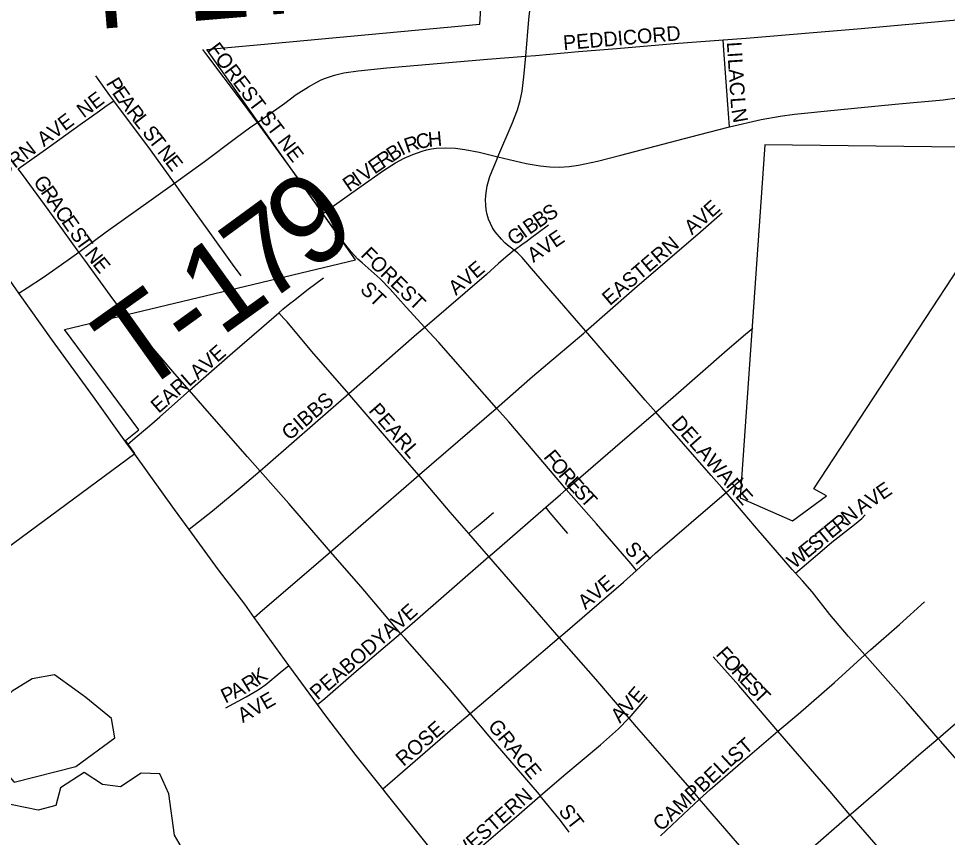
# Model space of a CAD drawing. Extents: x -51392 to 1635000, y 156707 to 696232.
# Drawn here: x 135989 to 139153, y 489385 to 492173 of the extents above; entities that cross this region are included whole.
import ezdxf

# ---------------------------------------------------------------- set-up
doc = ezdxf.new("R2010")
doc.units = 0
for name, color, linetype in [('GM_X_City_Street', 7, 'Continuous'), ('GM_X_City_Street_Text', 7, 'Continuous'), ('GM_X_Corporation', 7, 'Continuous'), ('GM_X_Major_River', 7, 'Continuous'), ('GM_X_Minor_Lake', 7, 'Continuous'), ('GM_X_State_Route', 7, 'Continuous'), ('GM_X_Township_Road', 7, 'Continuous'), ('GM_X_Township_Road_Text', 7, 'Continuous'), ('GM_X_Township_Subdivision', 7, 'Continuous'), ('GM_X_Township_Subdivision_Text', 7, 'Continuous')]:
    doc.layers.add(name, color=color, linetype=linetype)

msp = doc.modelspace()

# ---------------------------------------------------------------- linework, layer by layer
at = {"layer": 'GM_X_City_Street'}
for points in [[(137716.9, 492044.3), (137727.4, 492169.8), (137741.8, 492300), (137744, 492323.6)], [(138389, 492100.2), (138467.7, 492106.2), (138696, 492125.6), (138859.1, 492139.3), (139185.2, 492168.5), (139217.9, 492169.8), (139234.3, 492169.4), (139250.6, 492167.7), (139266.6, 492164.7), (139282.3, 492160), (139297.3, 492153.7), (139311.8, 492146), (139338.8, 492127.6), (139365.5, 492108.6), (139403.9, 492081.4)], [(137716.9, 492044.3), (137749.9, 492046.9), (137896.6, 492060.1), (138027.2, 492070.8), (138222.9, 492087.5), (138389, 492100.2)], [(138411.3, 491804.6), (138407.9, 491849.3), (138391.7, 492065), (138389, 492100.2)], [(138411.3, 491804.6), (138518.5, 491829.1), (138583.2, 491840.3), (138632, 491846.8), (138779.1, 491861.4), (138975.1, 491880.8), (139138.6, 491896.4), (139187.5, 491902.4), (139219.7, 491908.9), (139251.1, 491918.4), (139266.2, 491924.9), (139280.5, 491932.9), (139294, 491942.2), (139306.6, 491952.8), (139318.2, 491964.4), (139339.1, 491989.7), (139403.9, 492081.4)], [(136803.3, 491818.9), (136896.5, 491884.1), (136935.5, 491913.9), (136976.6, 491940.7), (137005.2, 491956.7), (137019.8, 491964), (137034.9, 491970.3), (137066.1, 491980.3), (137097.9, 491987.6), (137146.6, 491994.3), (137244.2, 492004.7), (137586.7, 492034.2), (137716.9, 492044.3)], [(137622.4, 491702.2), (137671, 491815.9), (137688.5, 491861.8), (137697.6, 491893.2), (137704.4, 491925.2), (137710.9, 491973.9), (137716.9, 492044.3)], [(137622.4, 491702.2), (137718.1, 491679.6), (137766.6, 491670.9), (137799.2, 491667.5), (137832, 491666.6), (137864.8, 491668.8), (137897.2, 491674), (137961.3, 491687.3), (138040.9, 491708.2), (138279.3, 491770.4), (138406.5, 491803.5), (138411.3, 491804.6)], [(137025.8, 491508.9), (137058, 491531.8), (137151.9, 491598.2), (137232, 491655.4), (137273.8, 491681.5), (137302.7, 491697.1), (137332.7, 491710.4), (137363.7, 491721.4), (137379.5, 491725.9), (137395.5, 491729.3), (137411.8, 491731.4), (137444.6, 491732.8), (137477.4, 491731.4), (137510, 491727.3), (137558.2, 491717.3), (137622.4, 491702.2)], [(137677.7, 491384), (137655.1, 491400.7), (137645.3, 491409.5), (137634, 491421.4), (137613.2, 491446.7), (137604.1, 491460.3), (137596.4, 491474.8), (137590.2, 491489.9), (137585.4, 491505.6), (137582.4, 491521.7), (137580.8, 491538), (137580.4, 491554.3), (137581, 491570.7), (137583, 491587), (137586, 491603.1), (137595.2, 491634.5), (137619.5, 491695.4), (137622.4, 491702.2)], [(137921.9, 491108.3), (138088, 491253.6), (138312.1, 491446.3), (138386.3, 491511)], [(137677.7, 491384), (137708.3, 491406.8), (137716.8, 491412.9), (137737.6, 491428.8), (137754.7, 491441.5), (137794, 491470.6)], [(137677.7, 491384), (137641.4, 491354), (137624.7, 491339), (137583.2, 491301.6), (137373.1, 491120.9)], [(137921.9, 491108.3), (137898.2, 491135.8), (137736.7, 491322.3), (137705.1, 491359.3), (137689.7, 491373.6), (137677.7, 491384)], [(137373.1, 491120.9), (137309.7, 491190.1), (137281.2, 491222), (137255.1, 491251.1), (137220.9, 491286.4), (137160.3, 491341.4), (137145.5, 491353.8)], [(136875.9, 491171.2), (136889.7, 491183.4), (136913.9, 491202.5), (136925.9, 491212.2), (136975.5, 491251.9), (137028.5, 491290.4)], [(136571.5, 490906.6), (136521.2, 490963.7), (136415.4, 491088.3), (136320.6, 491205)], [(136571.5, 490906.6), (136619.3, 490948.8), (136718.2, 491034.4), (136817.4, 491119.6), (136875.9, 491171.2)], [(137114.4, 490895.7), (136988.5, 491039.4), (136903.9, 491139.8), (136893, 491152), (136875.9, 491171.2)], [(137373.1, 491120.9), (137346.3, 491097.9), (137114.4, 490895.7)], [(137617.7, 490846.5), (137420.4, 491069.6), (137373.1, 491120.9)], [(138159.6, 490832.4), (138219.1, 490883.7), (138403.1, 491045.4), (138465.3, 491097.9), (138490.6, 491118.3)], [(137617.7, 490846.5), (137739.6, 490953.7), (137915, 491102.2), (137921.9, 491108.3)], [(138159.6, 490832.4), (138123.6, 490873.6), (137921.9, 491108.3)], [(136443.1, 490792.5), (136470.6, 490816.9), (136571.5, 490906.6)], [(136811.9, 490631.7), (136768.7, 490680.6), (136640.1, 490828.7), (136571.5, 490906.6)], [(137114.4, 490895.7), (136999.3, 490795.4), (136838.7, 490654.5), (136811.9, 490631.7)], [(137352.5, 490617.9), (137300, 490679.7), (137118.1, 490891.1), (137114.4, 490895.7)], [(137352.5, 490617.9), (137355.2, 490620), (137616.3, 490845.2), (137617.7, 490846.5)], [(137855.1, 490569.8), (137839.4, 490587.9), (137659.2, 490799.9), (137617.7, 490846.5)], [(137855.1, 490569.8), (138021.2, 490713.1), (138159.6, 490832.4)], [(138399.6, 490559.2), (138384.4, 490576.5), (138348.8, 490616.9), (138159.6, 490832.4)], [(136811.9, 490631.7), (136750.9, 490580), (136649.6, 490495.8), (136570.4, 490433.8)], [(137051.7, 490357.7), (137038.2, 490373.4), (136909.5, 490521.4), (136811.9, 490631.7)], [(137051.7, 490357.7), (137352.5, 490617.9)], [(137523.1, 490419.7), (137459.5, 490492.2), (137352.5, 490617.9)], [(138399.6, 490559.2), (138457.2, 490608.8)], [(139121.4, 489722.3), (139180.9, 489772.6), (139364.6, 489936), (139488.8, 490043), (139760.9, 490279.3), (139896.1, 490398.7), (140115.2, 490590.7)], [(137785, 490509.1), (137835.7, 490553), (137855.1, 490569.8)], [(138094.8, 490294.2), (138075.7, 490316.1), (137957.7, 490452.1), (137855.1, 490569.8)], [(138094.8, 490294.2), (138159.2, 490352.2), (138345.5, 490512.4), (138399.6, 490559.2)], [(138515.6, 490423.4), (138399.6, 490559.2)], [(137523.1, 490419.7), (137543, 490436.4), (137568.8, 490458), (137607.4, 490490.8)], [(137591.6, 490341.4), (137601.2, 490349.8), (137785, 490509.1)], [(137860, 490419.6), (137800.5, 490490.6), (137785, 490509.1)], [(138636.1, 490284.5), (138710.3, 490347.9), (138760.1, 490389.8), (138837.1, 490449.9), (138861.5, 490471.3), (138873.3, 490482.7)], [(137591.6, 490341.4), (137567.8, 490368.9), (137523.1, 490419.7)], [(138636.1, 490284.5), (138624.9, 490297.3), (138518.1, 490420.5), (138515.6, 490423.4)], [(136792, 490134.1), (136820.6, 490158.8), (136970.1, 490287.2), (137051.7, 490357.7)], [(137290.9, 490079.8), (137230.5, 490150.6), (137156.8, 490238.1), (137051.7, 490357.7)], [(137290.9, 490079.8), (137330.6, 490113.4), (137591.6, 490341.4)], [(137831.3, 490066.1), (137718.4, 490195.4), (137591.6, 490341.4)], [(137831.3, 490066.1), (137850.8, 490082.7), (138049.6, 490253.6), (138094.8, 490294.2)], [(138872.3, 490006.5), (138816.9, 490068.7), (138753.3, 490144.1), (138692.4, 490221.3), (138660, 490258), (138636.1, 490284.5)], [(138872.3, 490006.5), (138891, 490023.1), (138990.2, 490109.6), (139075.3, 490187.1)], [(137008.2, 489837), (137032.8, 489858.5), (137131, 489944.7), (137230.9, 490029), (137290.9, 490079.8)], [(137527.6, 489806.8), (137456, 489891.9), (137304.8, 490063.6), (137290.9, 490079.8)], [(137527.6, 489806.8), (137589.4, 489859), (137713.8, 489965.6), (137831.3, 490066.1)], [(138068.8, 489791.3), (137955.9, 489923.5), (137831.3, 490066.1)], [(138575.9, 489746.7), (138644.5, 489805.2), (138768.9, 489912.8), (138872.3, 490006.5)], [(139121.4, 489722.3), (139013.3, 489848.2), (138872.3, 490006.5)], [(138575.9, 489746.7), (138549.7, 489777.3), (138443, 489902.1), (138355.4, 490000.1)], [(136695.5, 489825.8), (136765.1, 489863.3), (136805.7, 489887.8), (136831.5, 489906.1), (136880.4, 489946.3), (136909.7, 489970.4)], [(138068.8, 489791.3), (138110.6, 489838.3), (138131.7, 489863.3)], [(137229.9, 489550.4), (137253.8, 489570.9), (137340.7, 489645.7), (137476.8, 489763.9), (137527.6, 489806.8)], [(137766.6, 489526.9), (137763.4, 489530.9), (137592.8, 489729.3), (137527.6, 489806.8)], [(137766.6, 489526.9), (137846.2, 489595.3), (137971.9, 489699.9), (138032.5, 489754.8), (138067.1, 489789.5), (138068.8, 489791.3)], [(138309.2, 489515), (138299.4, 489526.4), (138213.1, 489625.3), (138094.5, 489761.3), (138068.8, 489791.3)], [(138309.2, 489515), (138345.1, 489547.8), (138456.7, 489645.1), (138575.9, 489746.7)], [(138821.3, 489462.1), (138753.8, 489541.1), (138575.9, 489746.7)], [(138821.3, 489462.1), (138833.8, 489472.5), (138969.8, 489590.7), (139055.8, 489666.7), (139121.4, 489722.3)], [(139390.1, 489412.2), (139271.3, 489550.7), (139130.7, 489711.2), (139121.4, 489722.3)], [(137460.9, 489264.5), (137486.4, 489286.4), (137685, 489456.7), (137766.6, 489526.9)], [(137864.8, 489402.8), (137835.8, 489442.4), (137766.6, 489526.9)], [(138176.6, 489390.7), (138272.5, 489480.9), (138309.2, 489515)], [(138554.9, 489230.4), (138546, 489240.6), (138309.2, 489515)], [(138554.9, 489230.4), (138722, 489376.2), (138821.3, 489462.1)], [(139091.4, 489153.1), (138947.1, 489317.6), (138828.4, 489453.7), (138821.3, 489462.1)]]:
    msp.add_lwpolyline(points, dxfattribs=at)
at = {"layer": 'GM_X_Corporation'}
for points in [[(135520.3, 492188.3), (135566.7, 491914.9), (135580.3, 491867.6), (135603.4, 491805.1), (133833.5, 492028.3), (133821, 491861.8), (133926.1, 490810), (134830.5, 491047.4), (135185.7, 490756.7), (134987.1, 490585.9), (135134.2, 490381.2), (135761.9, 490232.9), (136385.4, 490691.9), (136353.3, 490736), (136399.6, 490772.9), (136145.5, 491114.3), (137137, 491351.3), (136630.3, 492067), (136652.2, 492069.4), (136801.6, 492083.2), (137560.3, 492153.6), (137599.5, 492759.5)], [(139780.3, 492322.4), (139382.9, 491732.9), (138531.2, 491743.3), (138447.1, 490541.3), (138625.9, 490463), (138741, 490547.5), (138698.5, 490572.2), (139573.9, 491906.7), (139880, 491837.7), (139911.2, 491565.8), (140072.1, 491715), (140073.3, 491866.9), (140221.8, 491863.1), (140226.3, 492428.6)]]:
    msp.add_lwpolyline(points, dxfattribs=at)
at = {"layer": 'GM_X_Major_River'}
msp.add_lwpolyline([(136552.1, 489338.4), (136520.3, 489392.6), (136500.8, 489532.9), (136471.1, 489601.1), (136407.1, 489603.3), (136336.8, 489557.5), (136274.8, 489565.7), (136213, 489605.9), (136132.7, 489554.1), (136116.5, 489494), (136056.4, 489478.2), (135922.4, 489504.7)], dxfattribs=at)
at = {"layer": 'GM_X_Minor_Lake'}
for points in [[(136036.1, 489925.1), (135967.9, 489883.2), (135845.3, 489753.3), (135865.1, 489695.2), (135974.7, 489572.6), (136185, 489626.1), (136317.5, 489723.8), (136305.7, 489790), (136218.8, 489860.9)], [(136180.9, 489888.7), (136112.2, 489938.9), (136036.1, 489925.1)], [(136218.8, 489860.9), (136180.9, 489888.7)]]:
    msp.add_lwpolyline(points, dxfattribs=at)
at = {"layer": 'GM_X_State_Route'}
for points in [[(136360.7, 490723.2), (136244.1, 490885.5), (136105.4, 491077.1), (135990.7, 491237.3), (135961.4, 491278.2), (135902.8, 491358.9), (135806.4, 491491.8), (135793.9, 491509.3), (135710.4, 491626), (135698, 491644.8), (135683, 491667.5), (135658.3, 491710.7), (135636.6, 491755.5), (135608.5, 491815.5)], [(136385, 490689.5), (136360.7, 490723.2)], [(136570.4, 490433.8), (136520, 490501.5), (136385, 490689.5)], [(137471, 489252.4), (137460.9, 489264.5), (137405.5, 489331.2), (137241.5, 489536), (137229.9, 489550.4), (137138.9, 489663.9), (137039.6, 489794.6), (137008.2, 489837), (136913, 489965.8), (136909.7, 489970.4), (136792, 490134.1), (136759.7, 490178.6), (136670, 490296.2), (136570.4, 490433.8)]]:
    msp.add_lwpolyline(points, dxfattribs=at)
at = {"layer": 'GM_X_Township_Road'}
for points in [[(136520.4, 491612.3), (136623, 491685.8), (136727.8, 491765.6), (136781, 491804.4), (136803.3, 491818.9)], [(136195, 491377.9), (136287.9, 491446.4), (136448.9, 491561), (136520.4, 491612.3)], [(135990.7, 491237.3), (136019.1, 491256.2), (136074, 491292.6), (136155.4, 491348.7), (136195, 491377.9)]]:
    msp.add_lwpolyline(points, dxfattribs=at)
at = {"layer": 'GM_X_Township_Subdivision'}
for points in [[(136803.3, 491818.9), (136755.9, 491883.5), (136627.7, 492054), (136617.6, 492066.9)], [(136314.3, 491892.6), (136300.7, 491910.8), (136253.1, 491978.1)], [(135988.2, 491661), (136080.6, 491726.8), (136199.1, 491811.7), (136264.8, 491859.1), (136291.6, 491877.3), (136314.3, 491892.6)], [(136520.4, 491612.3), (136439, 491725.8), (136314.3, 491892.6)], [(137025.8, 491508.9), (137015.1, 491524), (136939.8, 491631.6), (136803.3, 491818.9)], [(136195, 491377.9), (136090, 491523), (136002.3, 491641.3), (135988.2, 491661)], [(136747.5, 491297.2), (136718, 491337), (136641.4, 491444.5), (136544.8, 491578.2), (136520.4, 491612.3)], [(137145.5, 491353.8), (137122.1, 491378.8), (137091.4, 491417.2), (137025.8, 491508.9)], [(136320.6, 491205), (136301, 491231.5), (136214.7, 491350.7), (136195, 491377.9)], [(136360.7, 490723.2), (136387, 490745.3), (136428.1, 490780.1), (136443.1, 490792.5)]]:
    msp.add_lwpolyline(points, dxfattribs=at)

# ---------------------------------------------------------------- texts
at = {"layer": 'GM_X_City_Street_Text'}
for s, rotation, p in [('PEDDICORD', 4.8839, (137846.5, 492065.1)), ('L', 273.7093, (138402, 492092.2)), ('I', 273.6869, (138404.2, 492057.1)), ('L', 273.7054, (138405.6, 492035.1)), ('A', 273.6881, (138407.9, 492000)), ('C', 273.7149, (138410.8, 491956.1)), ('L', 273.8683, (138414.2, 491903.2)), ('N', 280.1976, (138417.3, 491862.1)), ('C', 13.7443, (137349.5, 491726.6)), ('H', 5.1116, (137386, 491735.7)), ('B', 34.1141, (137263.8, 491683.7)), ('I', 26.7125, (137295.1, 491705.1)), ('R', 18.7124, (137313.1, 491714.3)), ('R', 34.693, (137231.3, 491661.3)), ('V', 34.7059, (137166.2, 491616.2)), ('E', 34.691, (137202.4, 491641.2)), ('I', 34.6892, (137148.1, 491603.6)), ('R', 34.7069, (137115.6, 491581.1)), ('E', 41.9698, (138350.5, 491492.6)), ('S', 33.433, (137795.1, 491480.2)), ('V', 41.7958, (138317.6, 491463.1)), ('B', 34.8619, (137729.9, 491435.8)), ('B', 33.6021, (137762.1, 491458.3)), ('I', 35.7508, (137712.2, 491423.1)), ('A', 40.4169, (138283.1, 491433.7)), ('G', 35.7078, (137676.4, 491397.4)), ('AVE', 34.221, (137743.4, 491340.4)), ('EASTERN', 40.4606, (138003.4, 491193.2)), ('FOREST', 315.5386, (137152, 491365)), ('AVE', 40.0955, (137479.5, 491227.9)), ('ST', 315.5485, (137149.5, 491247)), ('E', 40.9176, (136666.1, 490999.9)), ('V', 41.0521, (136633, 490971)), ('A', 42.8019, (136601, 490941.4)), ('EARL', 41.1379, (136466.6, 490826.7)), ('GIBBS', 40.524, (136912, 490734.1)), ('PEARL', 310.9998, (137179.5, 490836.7)), ('DELAWARE', 311.3765, (138209.6, 490793.5)), ('F', 309.2453, (137775.2, 490679.3)), ('O', 309.2605, (137797.4, 490652)), ('R', 310.1736, (137825.8, 490617.3)), ('E', 312.2552, (137852.7, 490585.5)), ('S', 312.6658, (137876.6, 490559.2)), ('E', 34.2145, (138932.5, 490532.4)), ('T', 312.6598, (137900.5, 490533.3)), ('V', 34.2286, (138896.2, 490507.7)), ('N', 38.8775, (138816.1, 490447.7)), ('A', 34.8591, (138860.2, 490482.6)), ('R', 39.3282, (138785.5, 490422.6)), ('E', 39.3128, (138758.3, 490400.3)), ('T', 39.305, (138731.1, 490378)), ('ST', 310.7681, (138050.8, 490365.3)), ('E', 39.3301, (138676.6, 490333.4)), ('S', 39.305, (138703.8, 490355.7)), ('W', 39.3086, (138632.3, 490297.2)), ('AVE', 40.0955, (137920.7, 490158.4)), ('AVE', 41.5467, (137252.6, 490059.5)), ('PEABODY', 40.6761, (137008.2, 489850.5)), ('F', 311.5754, (138362, 490007.5)), ('O', 311.5476, (138385.4, 489981.1)), ('R', 311.6253, (138414.6, 489948.1)), ('K', 35.1247, (136805.8, 489900.8)), ('E', 312.7032, (138441.6, 489917.8)), ('A', 26.9725, (136726.3, 489856)), ('R', 31.7202, (136769.5, 489878.2)), ('S', 313.6648, (138466.1, 489891.2)), ('P', 25.9185, (136693.7, 489840.2)), ('AVE', 29.7858, (136753.3, 489774.1)), ('E', 49.6973, (138098.6, 489838)), ('T', 313.6824, (138490.5, 489865.8)), ('V', 47.5939, (138067.6, 489804)), ('A', 47.5635, (138037.9, 489771.5)), ('ROSE', 40.9674, (137300.8, 489624.4)), ('GRACE', 309.3918, (137585.7, 489762.3)), ('ST', 40.7779, (138431.6, 489635.1)), ('CAMPBELL', 42.8126, (138178.2, 489403.6)), ('WESTERN', 41.2319, (137493, 489300.6)), ('ST', 308.1015, (137826.2, 489474))]:
    msp.add_text(s, height=50, rotation=rotation, dxfattribs=at).set_placement(p)
at = {"layer": 'GM_X_Township_Road_Text'}
for s, rotation, p in [('T-176', 4.7626, (136186.3, 492130.7)), ('9', 36.4742, (136978, 491304.2)), ('7', 36.1691, (136828.6, 491195)), ('1', 35.7428, (136677.8, 491086.5)), ('T', 35.4315, (136394.7, 490884.3)), ('-', 35.714, (136578.5, 491015.1))]:
    msp.add_text(s, height=300, rotation=rotation, dxfattribs=at).set_placement(p)
at = {"layer": 'GM_X_Township_Subdivision_Text'}
for s, rotation, p in [('FOREST ST NE', 307.0487, (136631.6, 492067.4)), ('P', 300.9916, (136285.7, 491952.9)), ('E', 304.9148, (136305.9, 491919.6)), ('NE', 36.788, (136211.3, 491832.3)), ('A', 307.6288, (136327.6, 491888.7)), ('R', 307.716, (136354.5, 491853.8)), ('AVE', 37.0064, (136075.8, 491734.3)), ('L', 307.709, (136378.7, 491822.4)), ('S', 307.7055, (136408.3, 491784.1)), ('T', 307.7055, (136429.9, 491756.3)), ('CLYBURN', 37.5825, (135800.2, 491524.6)), ('N', 307.7097, (136459.5, 491718)), ('E', 307.7055, (136486.4, 491683.2)), ('G', 304.9683, (136037.5, 491617.2)), ('R', 304.9695, (136062.7, 491581.2)), ('A', 304.9683, (136085.4, 491548.7)), ('C', 304.9695, (136110.6, 491512.7)), ('E', 304.9711, (136133.3, 491480.2)), ('S', 304.9711, (136161, 491440.5)), ('T', 305.6491, (136181.6, 491411.2)), ('N', 308.6047, (136211.9, 491369.8)), ('E', 308.8441, (136239.4, 491335.3))]:
    msp.add_text(s, height=50, rotation=rotation, dxfattribs=at).set_placement(p)

doc.saveas('drawing.dxf')
